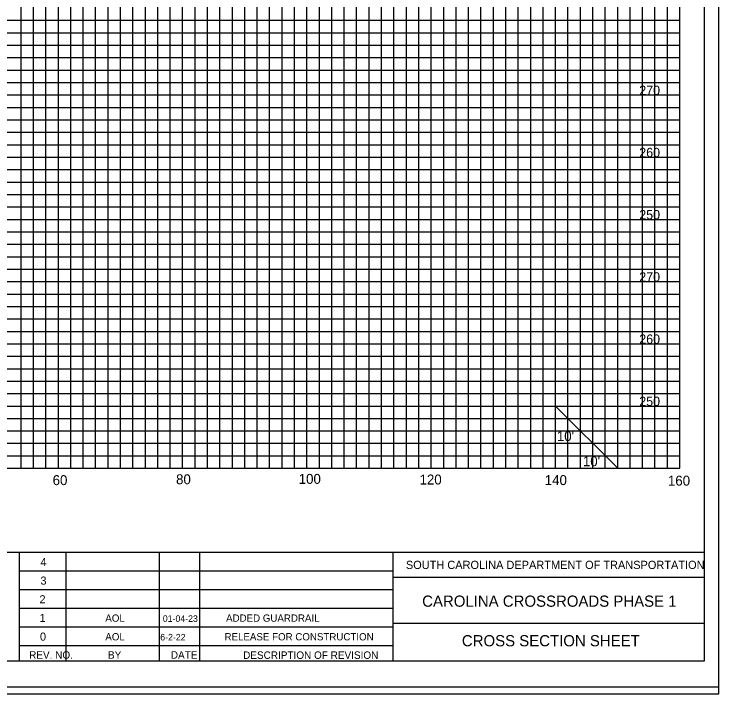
# Model space of a CAD drawing. Extents: x 967 to 1326, y 964 to 3704.
# Drawn here: x 1212.9 to 1326.3, y 1243.7 to 1353 of the extents above; entities that cross this region are included whole.
import ezdxf

# ---------------------------------------------------------------- set-up
doc = ezdxf.new("R2010")
doc.units = 0
for name, color, linetype in [('Default', 7, 'Continuous'), ('RD_SHT_Bndy', 7, 'Continuous'), ('RD_SHT_IplotShp', 7, 'Continuous'), ('RD_SHT_Misc1', 7, 'Continuous'), ('RD_SHT_MjGrid', 7, 'Continuous'), ('RD_SHT_MnGrid', 7, 'Continuous'), ('RD_SHT_TX', 7, 'Continuous'), ('RD_XS_TX_Station', 7, 'Continuous')]:
    doc.layers.add(name, color=color, linetype=linetype)

msp = doc.modelspace()

# ---------------------------------------------------------------- linework, layer by layer
at = {"layer": 'RD_SHT_Bndy'}
for p, q in [((1323.89, 1458.46), (1323.89, 1248.98)), ((996.11, 1266.49), (1323.89, 1266.49)), ((1213.76, 1248.94), (1213.76, 1266.49)), ((1221.26, 1248.95), (1221.26, 1266.48)), ((1236.26, 1248.95), (1236.26, 1266.48)), ((1242.76, 1248.95), (1242.76, 1266.48)), ((1273.88, 1248.98), (1273.88, 1266.49)), ((1213.76, 1263.48), (1273.88, 1263.48)), ((1323.93, 1262.43), (1273.88, 1262.43)), ((1213.76, 1260.48), (1273.88, 1260.48)), ((1213.76, 1257.48), (1273.88, 1257.48)), ((1213.76, 1254.48), (1273.88, 1254.48)), ((1323.89, 1255.04), (1273.88, 1255.04)), ((1213.76, 1251.48), (1273.88, 1251.48)), ((1323.89, 1248.98), (996.11, 1248.98))]:
    msp.add_line(p, q, dxfattribs=at)
at = {"layer": 'RD_SHT_IplotShp'}
for points in [[(967.41, 1243.72), (1326.28, 1243.72), (1326.28, 1463.72), (967.41, 1463.72)], [(988.52, 1244.84), (1326.28, 1244.84), (1326.28, 1462.6), (988.52, 1462.6)]]:
    msp.add_lwpolyline(points, close=True, dxfattribs=at)
at = {"layer": 'RD_SHT_MjGrid'}
for p, q in [((1220, 1280), (1220, 1450)), ((1230, 1280), (1230, 1450)), ((1240, 1280), (1240, 1450)), ((1250, 1280), (1250, 1450)), ((1260, 1280), (1260, 1450)), ((1270, 1280), (1270, 1450)), ((1280, 1280), (1280, 1450)), ((1290, 1280), (1290, 1450)), ((1300, 1280), (1300, 1450)), ((1310, 1280), (1310, 1450)), ((1320, 1280), (1320, 1450)), ((1000, 1350), (1320, 1350)), ((1000, 1340), (1320, 1340)), ((1000, 1330), (1320, 1330)), ((1000, 1320), (1320, 1320)), ((1000, 1310), (1320, 1310)), ((1000, 1300), (1320, 1300)), ((1000, 1290), (1320, 1290)), ((1000, 1280), (1320, 1280))]:
    msp.add_line(p, q, dxfattribs=at)
at = {"layer": 'RD_SHT_MnGrid'}
for p, q in [((1214, 1280), (1214, 1450)), ((1216, 1280), (1216, 1450)), ((1218, 1280), (1218, 1450)), ((1222, 1280), (1222, 1450)), ((1224, 1280), (1224, 1450)), ((1226, 1280), (1226, 1450)), ((1228, 1280), (1228, 1450)), ((1232, 1280), (1232, 1450)), ((1234, 1280), (1234, 1450)), ((1236, 1280), (1236, 1450)), ((1238, 1280), (1238, 1450)), ((1242, 1280), (1242, 1450)), ((1244, 1280), (1244, 1450)), ((1246, 1280), (1246, 1450)), ((1248, 1280), (1248, 1450)), ((1252, 1280), (1252, 1450)), ((1254, 1280), (1254, 1450)), ((1256, 1280), (1256, 1450)), ((1258, 1280), (1258, 1450)), ((1262, 1280), (1262, 1450)), ((1264, 1280), (1264, 1450)), ((1266, 1280), (1266, 1450)), ((1268, 1280), (1268, 1450)), ((1272, 1280), (1272, 1450)), ((1274, 1280), (1274, 1450)), ((1276, 1280), (1276, 1450)), ((1278, 1280), (1278, 1450)), ((1282, 1280), (1282, 1450)), ((1284, 1280), (1284, 1450)), ((1286, 1280), (1286, 1450)), ((1288, 1280), (1288, 1450)), ((1292, 1280), (1292, 1450)), ((1294, 1280), (1294, 1450)), ((1296, 1280), (1296, 1450)), ((1298, 1280), (1298, 1450)), ((1302, 1280), (1302, 1450)), ((1304, 1280), (1304, 1450)), ((1306, 1280), (1306, 1450)), ((1308, 1280), (1308, 1450)), ((1312, 1280), (1312, 1450)), ((1314, 1280), (1314, 1450)), ((1316, 1280), (1316, 1450)), ((1318, 1280), (1318, 1450)), ((1000, 1352), (1320, 1352)), ((1000, 1348), (1320, 1348)), ((1000, 1346), (1320, 1346)), ((1000, 1344), (1320, 1344)), ((1000, 1342), (1320, 1342)), ((1000, 1338), (1320, 1338)), ((1000, 1336), (1320, 1336)), ((1000, 1334), (1320, 1334)), ((1000, 1332), (1320, 1332)), ((1000, 1328), (1320, 1328)), ((1000, 1326), (1320, 1326)), ((1000, 1324), (1320, 1324)), ((1000, 1322), (1320, 1322)), ((1000, 1318), (1320, 1318)), ((1000, 1316), (1320, 1316)), ((1000, 1314), (1320, 1314)), ((1000, 1312), (1320, 1312)), ((1000, 1308), (1320, 1308)), ((1000, 1306), (1320, 1306)), ((1000, 1304), (1320, 1304)), ((1000, 1302), (1320, 1302)), ((1000, 1298), (1320, 1298)), ((1000, 1296), (1320, 1296)), ((1000, 1294), (1320, 1294)), ((1000, 1292), (1320, 1292)), ((1000, 1288), (1320, 1288)), ((1000, 1286), (1320, 1286)), ((1000, 1284), (1320, 1284)), ((1000, 1282), (1320, 1282))]:
    msp.add_line(p, q, dxfattribs=at)
at = {"layer": 'RD_SHT_TX'}
msp.add_line((1300, 1290), (1310, 1280), dxfattribs=at)
at = {"layer": 'RD_XS_TX_Station'}
msp.add_lwpolyline([(967.41, 1243.72), (1326.28, 1243.72), (1326.28, 1463.72), (967.41, 1463.72)], close=True, dxfattribs=at)

# ---------------------------------------------------------------- texts
at = {"layer": 'Default'}
for s, p in [('270', (1313.47, 1340)), ('260', (1313.47, 1330)), ('250', (1313.47, 1320)), ('270', (1313.47, 1310)), ('260', (1313.47, 1300)), ('250', (1313.47, 1290))]:
    msp.add_text(s, height=1.5, dxfattribs=at).set_placement(p)
at = {"layer": 'RD_SHT_Misc1'}
for s, height, p in [('AOL', 1.17, (1227.56, 1255.32)), ('01-04-23', 1.053, (1236.81, 1255.3)), ('ADDED GUARDRAIL', 1.17, (1246.99, 1255.32)), ('AOL', 1.17, (1227.56, 1252.32)), ('6-2-22', 1.053, (1236.4, 1252.31)), ('RELEASE FOR CONSTRUCTION', 1.17, (1246.74, 1252.32))]:
    msp.add_text(s, height=height, dxfattribs=at).set_placement(p)
at = {"layer": 'RD_SHT_TX'}
for s, height, p in [("10'", 1.6, (1300.21, 1284.36)), ("10'", 1.6, (1304.4, 1280.32)), ('60', 1.6, (1219.08, 1277.28)), ('80', 1.6, (1238.94, 1277.42)), ('100', 1.6, (1258.67, 1277.48)), ('120', 1.6, (1278.11, 1277.38)), ('140', 1.6, (1298.26, 1277.29)), ('160', 1.6, (1318.08, 1277.2)), ('4', 1.3, (1217.13, 1264.28)), ('SOUTH CAROLINA DEPARTMENT OF TRANSPORTATION', 1.32, (1275.92, 1263.8)), ('3', 1.3, (1217.13, 1261.28)), ('2', 1.3, (1216.97, 1258.28)), ('1', 1.3, (1216.97, 1255.28)), ('0', 1.3, (1217.05, 1252.28)), ('REV. NO.', 1.2, (1215.3, 1249.38)), ('BY', 1.2, (1227.99, 1249.38)), ('DATE', 1.2, (1238.1, 1249.38)), ('DESCRIPTION OF REVISION', 1.2, (1249.73, 1249.35))]:
    msp.add_text(s, height=height, dxfattribs=at).set_placement(p)
for s, p in [('CAROLINA CROSSROADS PHASE 1', (1278.54, 1257.73)), ('CROSS SECTION SHEET', (1284.93, 1251.37))]:
    msp.add_text(s, height=1.8, rotation=0, dxfattribs=at).set_placement(p)

doc.saveas('drawing.dxf')
